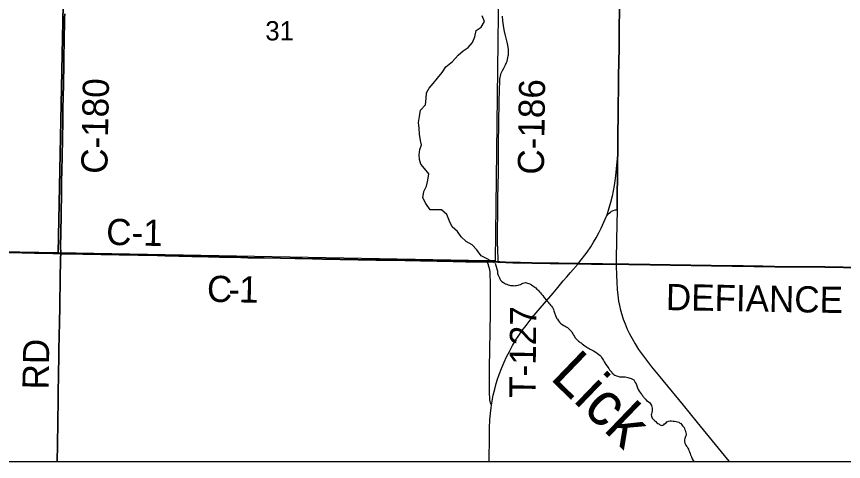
# Model space of a CAD drawing. Extents: x 0 to 34, y 0 to 22.
# Drawn here: x 5.615 to 7.41, y 14.1 to 15.064 of the extents above; entities that cross this region are included whole.
import ezdxf

# ---------------------------------------------------------------- set-up
doc = ezdxf.new("R2010")
doc.units = 0
for name, color, linetype in [('GM_X_Corporation', 7, 'Continuous'), ('GM_X_County_Road', 7, 'Continuous'), ('GM_X_County_Road_Text', 7, 'Continuous'), ('GM_X_Minor_River', 7, 'Continuous'), ('GM_X_Minor_River_Text', 7, 'Continuous'), ('GM_X_Section_Text', 7, 'Continuous'), ('GM_X_State_Route', 7, 'Continuous'), ('GM_X_Township_Road', 7, 'Continuous'), ('GM_X_Township_Road_Text', 7, 'Continuous'), ('GM_X_US_Route', 7, 'Continuous'), ('SH_Data', 7, 'Continuous')]:
    doc.layers.add(name, color=color, linetype=linetype)

msp = doc.modelspace()

# ---------------------------------------------------------------- linework, layer by layer
at = {"layer": 'GM_X_Corporation'}
for points in [[(4.7157, 15.5696), (5.726, 15.5556), (5.7061, 14.5519), (4.7065, 14.5692)], [(5.726, 15.5556), (6.6666, 15.5439), (6.6541, 14.5346), (6.6355, 14.5349), (5.7061, 14.5519)]]:
    msp.add_lwpolyline(points, close=True, dxfattribs=at)
for points in [[(5.5986, 14.5534), (5.654, 14.5523), (5.6944, 14.5514), (5.6995, 14.5512), (5.7114, 14.5509), (5.7111, 14.5662), (5.7112, 14.5712), (5.7112, 14.5774), (5.7113, 14.5836), (5.7114, 14.5874), (5.7115, 14.5923), (5.7116, 14.5992), (5.7117, 14.606), (5.712, 14.6228), (5.7121, 14.6271), (5.7122, 14.6315), (5.7123, 14.6364), (5.7124, 14.6408), (5.7124, 14.6451), (5.7125, 14.6501), (5.7125, 14.655), (5.7127, 14.6644), (5.7127, 14.6706), (5.7128, 14.6749), (5.7128, 14.6799), (5.713, 14.6873), (5.713, 14.6898), (5.7132, 14.6985), (5.7133, 14.7066), (5.7139, 14.7302), (5.7145, 14.7619), (5.7147, 14.7731), (5.715, 14.7867), (5.7153, 14.7998), (5.7154, 14.8116), (5.7156, 14.8253), (5.7159, 14.8476), (5.716, 14.8551), (5.7162, 14.8651), (5.7168, 14.8899), (5.7169, 14.8986), (5.7171, 14.9085), (5.7173, 14.921), (5.7175, 14.9334), (5.7178, 14.9458), (5.718, 14.9607), (5.7181, 14.9725), (5.7183, 14.9862), (5.7186, 15.0005), (5.7189, 15.0136), (5.7192, 15.0285), (5.7195, 15.0409), (5.7196, 15.0508), (5.7198, 15.0614), (5.72, 15.0701)], [(5.72, 15.0701), (5.7198, 15.0614), (5.7196, 15.0508), (5.7195, 15.0409), (5.7192, 15.0285), (5.7189, 15.0136), (5.7186, 15.0005), (5.7183, 14.9862), (5.7181, 14.9725), (5.718, 14.9607), (5.7178, 14.9458), (5.7175, 14.9334), (5.7173, 14.921), (5.7171, 14.9085), (5.7169, 14.8986), (5.7168, 14.8899), (5.7162, 14.8651), (5.716, 14.8551), (5.7159, 14.8476), (5.7156, 14.8253), (5.7154, 14.8116), (5.7153, 14.7998), (5.715, 14.7867), (5.7147, 14.7731), (5.7145, 14.7619), (5.7139, 14.7302), (5.7133, 14.7066), (5.7132, 14.6985), (5.713, 14.6898), (5.713, 14.6873), (5.7128, 14.6799), (5.7128, 14.6749), (5.7127, 14.6706), (5.7127, 14.6644), (5.7125, 14.655), (5.7125, 14.6501), (5.7124, 14.6451), (5.7124, 14.6408), (5.7123, 14.6364), (5.7122, 14.6315), (5.7121, 14.6271), (5.712, 14.6228), (5.7117, 14.606), (5.7116, 14.5992), (5.7115, 14.5923), (5.7114, 14.5874), (5.7113, 14.5836), (5.7112, 14.5774), (5.7112, 14.5712), (5.7111, 14.5662), (5.7114, 14.5509), (5.7595, 14.5498), (5.8378, 14.5482), (5.8795, 14.5474), (5.9211, 14.5466), (5.9379, 14.5464), (5.9677, 14.5457), (5.9957, 14.5449), (6.0317, 14.5442), (6.0553, 14.5436), (6.0821, 14.5432), (6.102, 14.5425), (6.1175, 14.5422), (6.1884, 14.5409), (6.2201, 14.5402), (6.2356, 14.54), (6.2791, 14.5389), (6.3947, 14.5368), (6.4208, 14.5366), (6.4307, 14.5365), (6.4463, 14.5365), (6.4587, 14.5362), (6.473, 14.5359), (6.4922, 14.5356), (6.5078, 14.5352), (6.5283, 14.5347), (6.5625, 14.5341), (6.5904, 14.5335), (6.6165, 14.5332), (6.6369, 14.5329), (6.642, 14.5328), (6.6603, 14.5324), (6.6641, 14.5323), (6.6768, 14.532), (6.6924, 14.5314), (6.7091, 14.5309), (6.734, 14.5303), (6.7539, 14.5299), (6.7731, 14.5298), (6.7924, 14.5295), (6.8086, 14.5293), (6.834, 14.5287), (6.8633, 14.5283), (6.8869, 14.528), (6.9074, 14.5279), (6.9167, 14.5279), (6.9441, 14.5277), (6.9901, 14.5269), (7.1232, 14.5246), (7.1686, 14.524), (7.1922, 14.5236), (7.2152, 14.5232), (7.2351, 14.5229), (7.2606, 14.5226), (7.3078, 14.5221), (7.3694, 14.5216), (7.4098, 14.5209), (7.4608, 14.5206)], [(2.1, 14.1), (5.7036, 14.1), (5.7042, 14.1363), (5.7057, 14.2339), (5.706, 14.2544), (5.7066, 14.2818), (5.7074, 14.3353), (5.7083, 14.3788), (5.7086, 14.3943), (5.7093, 14.4416), (5.7105, 14.4938), (5.7112, 14.5398), (5.7114, 14.5509), (5.6995, 14.5512), (5.6944, 14.5514), (5.654, 14.5523), (5.5986, 14.5534)], [(7.4608, 14.5206), (7.4098, 14.5209), (7.3694, 14.5216), (7.3078, 14.5221), (7.2606, 14.5226), (7.2351, 14.5229), (7.2152, 14.5232), (7.1922, 14.5236), (7.1686, 14.524), (7.1232, 14.5246), (6.9901, 14.5269), (6.9441, 14.5277), (6.9167, 14.5279), (6.9074, 14.5279), (6.8869, 14.528), (6.8633, 14.5283), (6.834, 14.5287), (6.8086, 14.5293), (6.7924, 14.5295), (6.7731, 14.5298), (6.7539, 14.5299), (6.734, 14.5303), (6.7091, 14.5309), (6.6924, 14.5314), (6.6768, 14.532), (6.6641, 14.5323), (6.6603, 14.5324), (6.642, 14.5328), (6.6369, 14.5329), (6.6165, 14.5332), (6.5904, 14.5335), (6.5625, 14.5341), (6.5283, 14.5347), (6.5078, 14.5352), (6.4922, 14.5356), (6.473, 14.5359), (6.4587, 14.5362), (6.4463, 14.5365), (6.4307, 14.5365), (6.4208, 14.5366), (6.3947, 14.5368), (6.2791, 14.5389), (6.2356, 14.54), (6.2201, 14.5402), (6.1884, 14.5409), (6.1175, 14.5422), (6.102, 14.5425), (6.0821, 14.5432), (6.0553, 14.5436), (6.0317, 14.5442), (5.9957, 14.5449), (5.9677, 14.5457), (5.9379, 14.5464), (5.9211, 14.5466), (5.8795, 14.5474), (5.8378, 14.5482), (5.7595, 14.5498), (5.7114, 14.5509), (5.6995, 14.5512), (5.6944, 14.5514), (5.654, 14.5523), (5.5986, 14.5534)], [(5.5986, 14.5534), (5.654, 14.5523), (5.6944, 14.5514), (5.6995, 14.5512), (5.7114, 14.5509), (5.7595, 14.5498), (5.8378, 14.5482), (5.8795, 14.5474), (5.9211, 14.5466), (5.9379, 14.5464), (5.9677, 14.5457), (5.9957, 14.5449), (6.0317, 14.5442), (6.0553, 14.5436), (6.0821, 14.5432), (6.102, 14.5425), (6.1175, 14.5422), (6.1884, 14.5409), (6.2201, 14.5402), (6.2356, 14.54), (6.2791, 14.5389), (6.3947, 14.5368), (6.4208, 14.5366), (6.4307, 14.5365), (6.4463, 14.5365), (6.4587, 14.5362), (6.473, 14.5359), (6.4922, 14.5356), (6.5078, 14.5352), (6.5283, 14.5347), (6.5625, 14.5341), (6.5904, 14.5335), (6.6165, 14.5332), (6.6369, 14.5329), (6.642, 14.5328), (6.6603, 14.5324), (6.6641, 14.5323), (6.6768, 14.532), (6.6924, 14.5314), (6.7091, 14.5309), (6.734, 14.5303), (6.7539, 14.5299), (6.7731, 14.5298), (6.7924, 14.5295), (6.8086, 14.5293), (6.834, 14.5287), (6.8633, 14.5283), (6.8869, 14.528), (6.9074, 14.5279), (6.9167, 14.5279), (6.9441, 14.5277), (6.9901, 14.5269), (7.1232, 14.5246), (7.1686, 14.524), (7.1922, 14.5236), (7.2152, 14.5232), (7.2351, 14.5229), (7.2606, 14.5226), (7.3078, 14.5221), (7.3694, 14.5216), (7.4098, 14.5209), (7.4608, 14.5206)], [(7.4608, 14.5206), (7.4098, 14.5209), (7.3694, 14.5216), (7.3078, 14.5221), (7.2606, 14.5226), (7.2351, 14.5229), (7.2152, 14.5232), (7.1922, 14.5236), (7.1686, 14.524), (7.1232, 14.5246), (6.9901, 14.5269), (6.9441, 14.5277), (6.9167, 14.5279), (6.9074, 14.5279), (6.8869, 14.528), (6.8633, 14.5283), (6.834, 14.5287), (6.8086, 14.5293), (6.7924, 14.5295), (6.7731, 14.5298), (6.7539, 14.5299), (6.734, 14.5303), (6.7091, 14.5309), (6.6924, 14.5314), (6.6768, 14.532), (6.6641, 14.5323), (6.6603, 14.5324), (6.642, 14.5328), (6.6369, 14.5329), (6.6165, 14.5332), (6.5904, 14.5335), (6.5625, 14.5341), (6.5283, 14.5347), (6.5078, 14.5352), (6.4922, 14.5356), (6.473, 14.5359), (6.4587, 14.5362), (6.4463, 14.5365), (6.4307, 14.5365), (6.4208, 14.5366), (6.3947, 14.5368), (6.2791, 14.5389), (6.2356, 14.54), (6.2201, 14.5402), (6.1884, 14.5409), (6.1175, 14.5422), (6.102, 14.5425), (6.0821, 14.5432), (6.0553, 14.5436), (6.0317, 14.5442), (5.9957, 14.5449), (5.9677, 14.5457), (5.9379, 14.5464), (5.9211, 14.5466), (5.8795, 14.5474), (5.8378, 14.5482), (5.7595, 14.5498), (5.7114, 14.5509), (5.7112, 14.5398), (5.7105, 14.4938), (5.7093, 14.4416), (5.7086, 14.3943), (5.7083, 14.3788), (5.7074, 14.3353), (5.7066, 14.2818), (5.706, 14.2544), (5.7057, 14.2339), (5.7042, 14.1363), (5.7036, 14.1), (8.9, 14.1)], [(2.1, 14.1), (8.9, 14.1)]]:
    msp.add_lwpolyline(points, dxfattribs=at)
at = {"layer": 'GM_X_County_Road'}
for points in [[(5.7116, 14.5503), (5.7114, 14.5657), (5.7114, 14.5707), (5.7115, 14.5769), (5.7116, 14.5831), (5.7116, 14.5868), (5.7117, 14.5918), (5.7118, 14.5986), (5.7119, 14.6055), (5.7122, 14.6222), (5.7123, 14.6266), (5.7124, 14.6309), (5.7125, 14.6359), (5.7126, 14.6402), (5.7126, 14.6446), (5.7127, 14.6495), (5.7128, 14.6545), (5.7129, 14.6638), (5.7129, 14.67), (5.713, 14.6744), (5.7131, 14.6793), (5.7132, 14.6868), (5.7132, 14.6893), (5.7134, 14.698), (5.7136, 14.706), (5.7141, 14.7296), (5.7147, 14.7613), (5.7149, 14.7725), (5.7152, 14.7862), (5.7155, 14.7992), (5.7157, 14.811), (5.7159, 14.8247), (5.7162, 14.8471), (5.7163, 14.8546), (5.7165, 14.8645), (5.717, 14.8893), (5.7172, 14.898), (5.7173, 14.908), (5.7175, 14.9204), (5.7178, 14.9328), (5.718, 14.9453), (5.7182, 14.9602), (5.7184, 14.972), (5.7186, 14.9857), (5.7189, 15), (5.7191, 15.013), (5.7195, 15.0279), (5.7197, 15.0403), (5.7199, 15.0503), (5.7201, 15.0609), (5.7202, 15.0696)], [(6.6606, 14.5318), (6.6604, 14.5382), (6.6598, 14.5583), (6.6593, 14.5755), (6.659, 14.5879), (6.6591, 14.6065), (6.6597, 14.632), (6.6599, 14.6494), (6.6602, 14.6705), (6.6611, 14.7264), (6.6618, 14.7836), (6.6625, 14.8371), (6.6632, 14.8768), (6.6638, 14.9092), (6.6641, 14.9207), (6.6644, 14.9252), (6.6646, 14.9289), (6.665, 14.9322), (6.6655, 14.935), (6.6664, 14.9385), (6.6675, 14.9417), (6.6698, 14.947), (6.6727, 14.9525), (6.6769, 14.9598), (6.679, 14.9644), (6.6802, 14.9679), (6.6811, 14.9712), (6.6817, 14.9745), (6.6825, 14.9788), (6.6828, 14.9815), (6.6829, 14.9855), (6.683, 14.988), (6.683, 14.9902), (6.6828, 14.9933), (6.6825, 14.9971), (6.6817, 15.002), (6.6803, 15.0088), (6.6758, 15.0262), (6.6752, 15.0286), (6.6737, 15.0353), (6.672, 15.045), (6.6707, 15.0548), (6.6699, 15.0653)], [(5.7116, 14.5503), (5.7597, 14.5492), (5.838, 14.5476), (5.8797, 14.5468), (5.9213, 14.5461), (5.9381, 14.5458), (5.968, 14.5451), (5.9959, 14.5444), (6.032, 14.5437), (6.0556, 14.543), (6.0823, 14.5426), (6.1022, 14.542), (6.1177, 14.5416), (6.1886, 14.5404), (6.2203, 14.5397), (6.2358, 14.5395), (6.2794, 14.5383), (6.3949, 14.5363), (6.421, 14.536), (6.431, 14.5359), (6.4465, 14.5359), (6.459, 14.5357), (6.4732, 14.5353), (6.4925, 14.535), (6.508, 14.5346), (6.5285, 14.5341), (6.5627, 14.5335), (6.5907, 14.5329), (6.6168, 14.5327), (6.6372, 14.5324)], [(6.6372, 14.5324), (6.6423, 14.5323), (6.6606, 14.5318)], [(6.6606, 14.5318), (6.6643, 14.5317), (6.6771, 14.5314), (6.6926, 14.5308), (6.7094, 14.5304), (6.7342, 14.5297), (6.7541, 14.5294), (6.7734, 14.5292), (6.7926, 14.5289), (6.8088, 14.5288), (6.8342, 14.5282)], [(6.8342, 14.5282), (6.8635, 14.5277), (6.8872, 14.5275), (6.9077, 14.5274), (6.917, 14.5273)], [(6.917, 14.5273), (6.9444, 14.5271), (6.9904, 14.5263), (7.1234, 14.5241), (7.1688, 14.5235), (7.1924, 14.5231), (7.2154, 14.5226), (7.2353, 14.5224), (7.2608, 14.5221), (7.3081, 14.5215), (7.3696, 14.5211), (7.41, 14.5203), (7.461, 14.5201), (7.5201, 14.5192), (7.5655, 14.5187), (7.6283, 14.5174), (7.6591, 14.517)]]:
    msp.add_lwpolyline(points, dxfattribs=at)
at = {"layer": 'GM_X_Minor_River'}
for points in [[(6.6525, 14.5307), (6.6352, 14.5401), (6.6236, 14.5456), (6.6144, 14.5587), (6.604, 14.5695), (6.5912, 14.5766), (6.5804, 14.5871), (6.5723, 14.5986), (6.5607, 14.6087), (6.5553, 14.6209), (6.5495, 14.6355), (6.5379, 14.6455), (6.525, 14.645), (6.5129, 14.6456), (6.5037, 14.6591), (6.4971, 14.6717), (6.4992, 14.685), (6.5055, 14.6966), (6.5081, 14.7095), (6.5102, 14.7235), (6.5006, 14.735), (6.4932, 14.7446), (6.49, 14.7542), (6.4894, 14.7648), (6.4908, 14.7762), (6.4944, 14.786), (6.4919, 14.7959), (6.4903, 14.8096), (6.4894, 14.8221), (6.4881, 14.8346), (6.4899, 14.8479), (6.492, 14.8611), (6.5029, 14.8727), (6.5047, 14.8863), (6.5049, 14.8988), (6.5108, 14.9093), (6.5197, 14.9194), (6.5294, 14.9306), (6.5391, 14.9433), (6.5473, 14.9552), (6.5619, 14.9667), (6.5736, 14.9805), (6.5848, 14.9902), (6.5959, 14.9975), (6.6048, 15.0084), (6.61, 15.0204), (6.6133, 15.0344), (6.6237, 15.041), (6.6311, 15.0534), (6.6257, 15.066)], [(6.654, 14.5299), (6.6591, 14.5125), (6.6591, 14.5118), (6.6594, 14.5076), (6.6608, 14.5038), (6.6619, 14.5011), (6.6634, 14.498), (6.6641, 14.4961), (6.6659, 14.493), (6.6689, 14.4899), (6.6722, 14.4875), (6.6745, 14.4863), (6.6767, 14.4852), (6.6793, 14.484), (6.6827, 14.4831), (6.685, 14.4823), (6.6873, 14.4815), (6.6892, 14.4814), (6.6922, 14.481), (6.6948, 14.4809), (6.6975, 14.4812), (6.7006, 14.4815), (6.704, 14.4818), (6.7063, 14.4826), (6.7093, 14.4836), (6.7116, 14.4851), (6.7143, 14.4865), (6.7174, 14.4872), (6.7197, 14.4876), (6.7223, 14.4871), (6.7242, 14.4867), (6.7276, 14.4855), (6.7306, 14.4843), (6.7332, 14.4831), (6.7358, 14.4807), (6.7381, 14.4791), (6.7403, 14.4776), (6.7422, 14.476), (6.7448, 14.4737), (6.7466, 14.4721), (6.7489, 14.4698), (6.7507, 14.4678), (6.7529, 14.4651), (6.7551, 14.4624), (6.7574, 14.4593), (6.7599, 14.4558), (6.7633, 14.4519), (6.7662, 14.4481), (6.7692, 14.445), (6.771, 14.443), (6.7725, 14.4411), (6.7743, 14.4384), (6.7762, 14.4364), (6.7784, 14.4334), (6.7798, 14.431), (6.7806, 14.4291), (6.7816, 14.4261), (6.7823, 14.4241), (6.7831, 14.4222), (6.7852, 14.4161), (6.7863, 14.413), (6.7873, 14.4107), (6.7892, 14.408), (6.7914, 14.4046), (6.794, 14.4022), (6.7962, 14.3999), (6.7995, 14.3971), (6.8029, 14.3948), (6.8059, 14.3932), (6.8085, 14.392), (6.8111, 14.39), (6.8134, 14.3881), (6.8164, 14.3854), (6.8186, 14.383), (6.8204, 14.3807), (6.8211, 14.3788), (6.8226, 14.3769), (6.8244, 14.3738), (6.8263, 14.3707), (6.8274, 14.3688), (6.8299, 14.3657), (6.8329, 14.3626), (6.8348, 14.361), (6.837, 14.359), (6.8389, 14.3575), (6.8407, 14.3567), (6.8433, 14.3547), (6.8486, 14.3508), (6.8508, 14.3492), (6.8531, 14.348), (6.8553, 14.3461), (6.8583, 14.3449), (6.8605, 14.3433), (6.8632, 14.3421), (6.8654, 14.3409), (6.8677, 14.3397), (6.871, 14.3373), (6.8729, 14.3365), (6.8763, 14.3342), (6.8793, 14.3318), (6.8819, 14.3295)], [(6.8819, 14.3295), (6.8841, 14.3271), (6.8852, 14.3252), (6.8874, 14.3221), (6.8892, 14.3187), (6.891, 14.316), (6.8925, 14.3137), (6.8947, 14.3102), (6.8973, 14.3063), (6.8987, 14.304), (6.9006, 14.3013), (6.9024, 14.2982), (6.9042, 14.2963), (6.9072, 14.2932), (6.9083, 14.2912), (6.9101, 14.2897), (6.912, 14.2881), (6.9139, 14.2873), (6.9173, 14.2853), (6.9203, 14.2845), (6.9241, 14.2837), (6.9267, 14.2836), (6.9362, 14.283), (6.9392, 14.2825), (6.9419, 14.2817), (6.9445, 14.2813), (6.9475, 14.2804), (6.9494, 14.2796), (6.9524, 14.2784), (6.955, 14.2768), (6.9565, 14.2741), (6.9583, 14.2714), (6.9601, 14.268), (6.9608, 14.2657), (6.9619, 14.2638), (6.9626, 14.2618), (6.9633, 14.2596), (6.9648, 14.2561), (6.9666, 14.2526), (6.9688, 14.2495), (6.971, 14.2468), (6.9729, 14.2445), (6.9743, 14.2422), (6.9758, 14.2403), (6.9769, 14.2383), (6.9802, 14.2348), (6.9824, 14.2321), (6.9866, 14.2297), (6.9892, 14.2278), (6.991, 14.2247), (6.9932, 14.2209), (6.9943, 14.2182), (6.995, 14.2151), (6.9949, 14.2121), (6.9948, 14.2098), (6.994, 14.2064), (6.9935, 14.2034), (6.9931, 14.2011), (6.9934, 14.1981), (6.9941, 14.1958), (6.9952, 14.1935), (6.9978, 14.1907), (7.0008, 14.188), (7.0026, 14.1864), (7.0052, 14.1837), (7.0075, 14.1825), (7.0093, 14.1813), (7.0112, 14.1798), (7.0138, 14.1786), (7.0161, 14.1781), (7.0184, 14.1785), (7.0203, 14.1792), (7.0219, 14.1814), (7.025, 14.184), (7.0269, 14.1855), (7.0288, 14.1866), (7.0307, 14.1873), (7.0338, 14.188), (7.0372, 14.1879), (7.0406, 14.1874), (7.0436, 14.187), (7.0467, 14.1865), (7.0501, 14.1857), (7.0527, 14.1849), (7.0546, 14.1837), (7.0568, 14.1821), (7.0594, 14.1794), (7.0609, 14.1775), (7.0642, 14.1732), (7.0649, 14.1709), (7.0663, 14.1678), (7.0674, 14.1652), (7.0677, 14.1621), (7.0684, 14.159), (7.0684, 14.1568), (7.0675, 14.1541), (7.0663, 14.1515), (7.0655, 14.1496), (7.0651, 14.1466), (7.0654, 14.1435), (7.0661, 14.1397)], [(7.0661, 14.1397), (7.0668, 14.1378), (7.0682, 14.1351), (7.0697, 14.1332), (7.0708, 14.1313), (7.0723, 14.1289), (7.0737, 14.1266), (7.0748, 14.1236), (7.0762, 14.1205), (7.0773, 14.1174), (7.0784, 14.114), (7.0802, 14.1101), (7.082, 14.1055), (7.0842, 14.1017), (7.085, 14.1)]]:
    msp.add_lwpolyline(points, dxfattribs=at)
at = {"layer": 'GM_X_State_Route'}
for points in [[(6.9296, 15.5426), (6.9292, 15.504), (6.9286, 15.4555), (6.9281, 15.4219), (6.9279, 15.3859), (6.9275, 15.3598), (6.9258, 15.2342), (6.9253, 15.1863), (6.9239, 15.0781), (6.9236, 15.0402), (6.923, 14.9967), (6.9221, 14.9352), (6.9218, 14.8979), (6.9215, 14.8823), (6.921, 14.8425), (6.9207, 14.817), (6.9205, 14.7947), (6.9203, 14.7804)], [(6.9202, 14.7707), (6.9199, 14.7499), (6.9187, 14.6456)], [(6.9203, 14.7804), (6.9202, 14.7723), (6.9202, 14.7707)], [(6.9187, 14.6456), (6.9174, 14.5801), (6.9171, 14.5378), (6.917, 14.5273)], [(6.917, 14.5273), (6.917, 14.5241), (6.9175, 14.5035), (6.9179, 14.4885), (6.9189, 14.4723), (6.9201, 14.4605), (6.9219, 14.4476), (6.9238, 14.4378), (6.9261, 14.428), (6.9289, 14.4185), (6.9322, 14.4084), (6.9362, 14.3979), (6.9409, 14.387), (6.9458, 14.3769), (6.9512, 14.3664), (6.9577, 14.355), (6.9654, 14.3429), (6.9736, 14.3311), (6.9827, 14.3192), (6.9938, 14.305), (7.0116, 14.2834), (7.0179, 14.2757)], [(7.0179, 14.2757), (7.062, 14.2218), (7.0927, 14.1843), (7.1249, 14.1448), (7.1577, 14.1049), (7.1618, 14.1)]]:
    msp.add_lwpolyline(points, dxfattribs=at)
at = {"layer": 'GM_X_Township_Road'}
for points in [[(4.7097, 14.5684), (4.7383, 14.5677), (4.8035, 14.5663), (4.8532, 14.5655), (4.8955, 14.565), (4.9583, 14.564), (5.0012, 14.5635), (5.1025, 14.5621), (5.1441, 14.5612), (5.2894, 14.5587), (5.323, 14.5582), (5.4086, 14.5566), (5.446, 14.5561), (5.5504, 14.5537), (5.5989, 14.5529), (5.6542, 14.5517), (5.6946, 14.5508), (5.6998, 14.5507), (5.7116, 14.5503)], [(5.7039, 14.1), (5.7044, 14.1358), (5.7059, 14.2334), (5.7062, 14.2539), (5.7068, 14.2812), (5.7076, 14.3347), (5.7086, 14.3782), (5.7089, 14.3938), (5.7096, 14.441), (5.7107, 14.4932), (5.7114, 14.5392), (5.7116, 14.5503)], [(5.7116, 14.5503), (5.7597, 14.5492), (5.838, 14.5476), (5.8797, 14.5468), (5.9213, 14.5461), (5.9381, 14.5458), (5.968, 14.5451), (5.9959, 14.5444), (6.032, 14.5437), (6.0556, 14.543), (6.0823, 14.5426), (6.1022, 14.542), (6.1177, 14.5416), (6.1886, 14.5404), (6.2203, 14.5397), (6.2358, 14.5395), (6.2794, 14.5383), (6.3949, 14.5363), (6.421, 14.536), (6.431, 14.5359), (6.4465, 14.5359), (6.459, 14.5357), (6.4732, 14.5353), (6.4925, 14.535), (6.508, 14.5346), (6.5285, 14.5341), (6.5627, 14.5335), (6.5907, 14.5329), (6.6168, 14.5327), (6.6372, 14.5324)], [(6.6462, 14.2222), (6.644, 14.2267), (6.643, 14.2301), (6.6426, 14.2335), (6.6424, 14.2367), (6.6421, 14.2486), (6.6419, 14.2732), (6.6422, 14.3037), (6.6435, 14.3807), (6.6442, 14.4223), (6.6444, 14.4415), (6.6444, 14.462), (6.6442, 14.4781), (6.6441, 14.4887), (6.6436, 14.5048), (6.6432, 14.5104), (6.6425, 14.5153), (6.6414, 14.5202), (6.6399, 14.5249), (6.6395, 14.5261), (6.6372, 14.5324)], [(6.6372, 14.5324), (6.6423, 14.5323), (6.6606, 14.5318)], [(6.6606, 14.5318), (6.6643, 14.5317), (6.6771, 14.5314), (6.6926, 14.5308), (6.7094, 14.5304), (6.7342, 14.5297), (6.7541, 14.5294), (6.7734, 14.5292), (6.7926, 14.5289), (6.8088, 14.5288), (6.8342, 14.5282)], [(6.8342, 14.5282), (6.8635, 14.5277), (6.8872, 14.5275), (6.9077, 14.5274), (6.917, 14.5273)], [(6.917, 14.5273), (6.9444, 14.5271), (6.9904, 14.5263), (7.1234, 14.5241), (7.1688, 14.5235), (7.1924, 14.5231), (7.2154, 14.5226), (7.2353, 14.5224), (7.2608, 14.5221), (7.3081, 14.5215), (7.3696, 14.5211), (7.41, 14.5203), (7.461, 14.5201), (7.5201, 14.5192), (7.5655, 14.5187), (7.6283, 14.5174), (7.6591, 14.517)]]:
    msp.add_lwpolyline(points, dxfattribs=at)
at = {"layer": 'GM_X_US_Route'}
for points in [[(6.9203, 14.7804), (6.9205, 14.7947), (6.9207, 14.817), (6.921, 14.8425), (6.9215, 14.8823), (6.9218, 14.8979), (6.9221, 14.9352), (6.923, 14.9967), (6.9236, 15.0402), (6.9239, 15.0781), (6.9253, 15.1863), (6.9258, 15.2342), (6.9275, 15.3598), (6.9279, 15.3859), (6.9281, 15.4219), (6.9286, 15.4555), (6.9292, 15.504), (6.9296, 15.5426)], [(6.9202, 14.7707), (6.9175, 14.7419), (6.9154, 14.7192), (6.9141, 14.7081), (6.9127, 14.6984), (6.9106, 14.6868), (6.9079, 14.6747), (6.9046, 14.6615), (6.9008, 14.6487), (6.8956, 14.6314)], [(6.9187, 14.6456), (6.9199, 14.7499), (6.9202, 14.7707)], [(6.9202, 14.7707), (6.9202, 14.7723), (6.9203, 14.7804)], [(6.8956, 14.6314), (6.8989, 14.6354), (6.9016, 14.6381), (6.9042, 14.6403), (6.9067, 14.6421), (6.9088, 14.6433), (6.9111, 14.6442), (6.9145, 14.6451), (6.9187, 14.6456)], [(6.8342, 14.5282), (6.8358, 14.5302), (6.8538, 14.5539), (6.8616, 14.5651), (6.8679, 14.5751), (6.8735, 14.5848), (6.879, 14.5952), (6.8839, 14.6053), (6.8956, 14.6314)], [(6.6415, 14.1), (6.6417, 14.1546), (6.6421, 14.1757), (6.6426, 14.1871), (6.6427, 14.1906), (6.6438, 14.2036), (6.6453, 14.2159), (6.6462, 14.2222), (6.6502, 14.2434), (6.6533, 14.2567), (6.6565, 14.2686), (6.6594, 14.2781), (6.6628, 14.2881), (6.6679, 14.3014), (6.6737, 14.3151), (6.6791, 14.327), (6.685, 14.3386), (6.692, 14.351), (6.6993, 14.3633), (6.7053, 14.3727), (6.7124, 14.3828), (6.7213, 14.3948), (6.7348, 14.4118), (6.7475, 14.4271), (6.7658, 14.4483), (6.7798, 14.4649), (6.787, 14.4735), (6.8018, 14.4911), (6.8095, 14.5), (6.8177, 14.5095), (6.8342, 14.5282)]]:
    msp.add_lwpolyline(points, dxfattribs=at)
at = {"layer": 'SH_Data'}
msp.add_line((2.1, 14.1), (8.9, 14.1), dxfattribs=at)

# ---------------------------------------------------------------- texts
at = {"layer": 'GM_X_County_Road_Text'}
for s, height, rotation, p in [('C-180', 0.05682, 88.8983, (5.8124, 14.723)), ('C-186', 0.05682, 89.1904, (6.7599, 14.7213)), ('C-1', 0.05682, 358.7779, (5.8096, 14.5694)), ('C', 0.0568, 358.7908, (6.0283, 14.4461)), ('1', 0.0568, 358.8626, (6.0978, 14.4447)), ('DEFIANCE', 0.05682, 359.0219, (7.0244, 14.4281)), ('-', 0.0568, 358.8513, (6.0747, 14.4452))]:
    msp.add_text(s, height=height, rotation=rotation, dxfattribs=at).set_placement(p)
at = {"layer": 'GM_X_Minor_River_Text'}
msp.add_text('Lick', height=0.09475, rotation=316.0476, dxfattribs=at).set_placement((6.7711, 14.2798))
at = {"layer": 'GM_X_Section_Text'}
msp.add_text('31', height=0.04186, rotation=0, dxfattribs=at).set_placement((6.1554, 15.0125))
at = {"layer": 'GM_X_Township_Road_Text'}
for s, rotation, p in [('T-127', 89.4437, (6.7416, 14.2376)), ('RD', 89.0151, (5.685, 14.2555))]:
    msp.add_text(s, height=0.05682, rotation=rotation, dxfattribs=at).set_placement(p)

doc.saveas('drawing.dxf')
